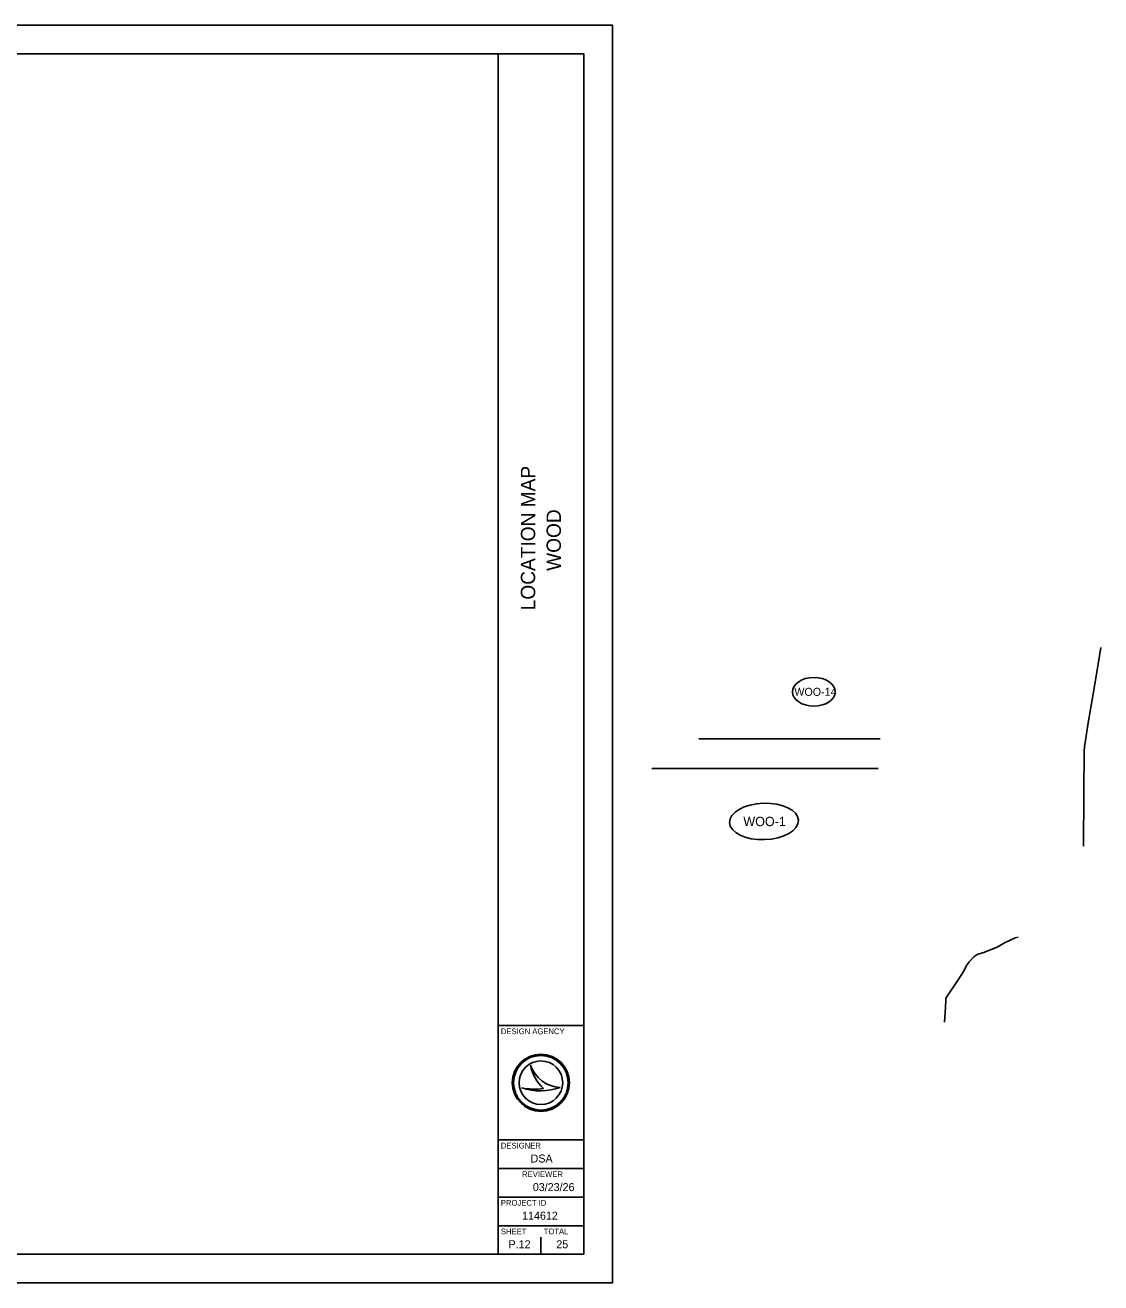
# Model space of a CAD drawing. Extents: x 0 to 851, y 0 to 440.
# Drawn here: x 474.6 to 850.9, y 0 to 440 of the extents above; entities that cross this region are included whole.
import ezdxf

# ---------------------------------------------------------------- set-up
doc = ezdxf.new("R2010")
doc.units = 0
for name, color, linetype in [('RD_P_Fence', 7, 'Continuous'), ('SH_Border', 7, 'Continuous'), ('SH_Cut_Line', 7, 'Continuous'), ('SH_Data', 7, 'Continuous')]:
    doc.layers.add(name, color=color, linetype=linetype)

msp = doc.modelspace()

# ---------------------------------------------------------------- linework, layer by layer
at = {"layer": 'RD_P_Fence'}
for p, q in [((710.26, 190.35), (773.73, 190.35)), ((693.77, 179.92), (773.01, 179.95))]:
    msp.add_line(p, q, dxfattribs=at)
for points in [[(844.8, 152.74), (844.9, 171.12), (845.05, 185.98), (845.11, 187.55), (846.49, 195.87), (848.52, 208.1), (849.91, 216.61), (850.87, 222.31)], [(796.15, 91.15), (796.37, 94.59), (796.6, 98.65), (796.67, 99.6), (801.14, 106.35), (803.02, 109.33), (803.83, 111.07), (804.8, 112.26), (806.45, 114.07), (807.82, 115.01), (809.64, 115.49), (814.6, 117.43), (817.35, 119.02), (818.44, 119.55), (819.14, 119.89), (820.96, 120.75), (822, 120.95)]]:
    msp.add_lwpolyline(points, dxfattribs=at)
for centre, major_axis, ratio in [((750.49, 206.77), (7.5, 0), 0.666667), ((733.04, 161.42), (12.06, 0.4), 0.528422)]:
    msp.add_ellipse(centre, major_axis=major_axis, ratio=ratio, dxfattribs=at)
at = {"layer": 'SH_Border'}
for p, q in [((640, 10), (640, 430)), ((640, 90), (670, 90)), ((640, 50), (670, 50)), ((640, 40), (670, 40)), ((640, 30), (670, 30)), ((640, 20), (670, 20))]:
    msp.add_line(p, q, dxfattribs=at)
msp.add_lwpolyline([(30, 430), (670, 430), (670, 10), (30, 10)], close=True, dxfattribs=at)
at = {"layer": 'SH_Cut_Line'}
msp.add_lwpolyline([(0, 0), (680, 0), (680, 440), (0, 440)], close=True, dxfattribs=at)
at = {"layer": 'SH_Data'}
for p, q in [((651.35, 76.19), (651.35, 76.19)), ((648.34, 68.19), (648.34, 68.19)), ((655, 70), (655, 70)), ((661.75, 68.37), (661.75, 68.37)), ((647.5, 13.5), (647.5, 13.5)), ((655, 10), (655, 16))]:
    msp.add_line(p, q, dxfattribs=at)
for radius in [10, 9.54, 9.54, 7.64]:
    msp.add_circle((655, 70), radius, dxfattribs=at)
for centre, radius, start, end in [((662.32, 79.95), 11.6, 198.9257, 198.9319), ((666.93, 79.4), 15.91, 191.6379, 191.6421), ((662.32, 79.95), 11.6, 198.9319, 267.1657), ((666.93, 79.4), 15.91, 191.6421, 226.0947), ((654.79, 87.4), 20.26, 251.4576, 290.0832), ((652.96, 93.09), 25.32, 259.4964, 259.4995), ((654.79, 87.4), 20.26, 251.4527, 251.4576), ((652.96, 93.09), 25.32, 259.4995, 276.6672)]:
    msp.add_arc(centre, radius, start, end, dxfattribs=at)

# ---------------------------------------------------------------- texts
at = {"layer": 'RD_P_Fence'}
for s, height, p in [('WOO-14', 2.8, (743.65, 205.37)), ('WOO-1', 3.283, (725.82, 159.77))]:
    msp.add_text(s, height=height, dxfattribs=at).set_placement(p)
at = {"layer": 'SH_Data'}
for s, p in [('LOCATION MAP', (653, 235.29)), ('WOOD', (662, 249.08))]:
    msp.add_text(s, height=5, rotation=90, dxfattribs=at).set_placement(p)
for s, height, p in [('DESIGN AGENCY', 2, (641, 87)), ('DESIGNER', 2, (641, 47)), ('DSA', 2.8, (651.41, 42.1)), ('REVIEWER', 2, (648.44, 37)), ('03/23/26', 2.8, (652.18, 32.1)), ('PROJECT ID', 2, (641, 27)), ('114612', 2.8, (648.42, 22.1)), ('SHEET', 2, (641, 17)), ('TOTAL', 2, (656, 17)), ('P.12', 2.8, (643.69, 12.1)), ('25', 2.8, (660.39, 12.1))]:
    msp.add_text(s, height=height, dxfattribs=at).set_placement(p)

doc.saveas('drawing.dxf')
